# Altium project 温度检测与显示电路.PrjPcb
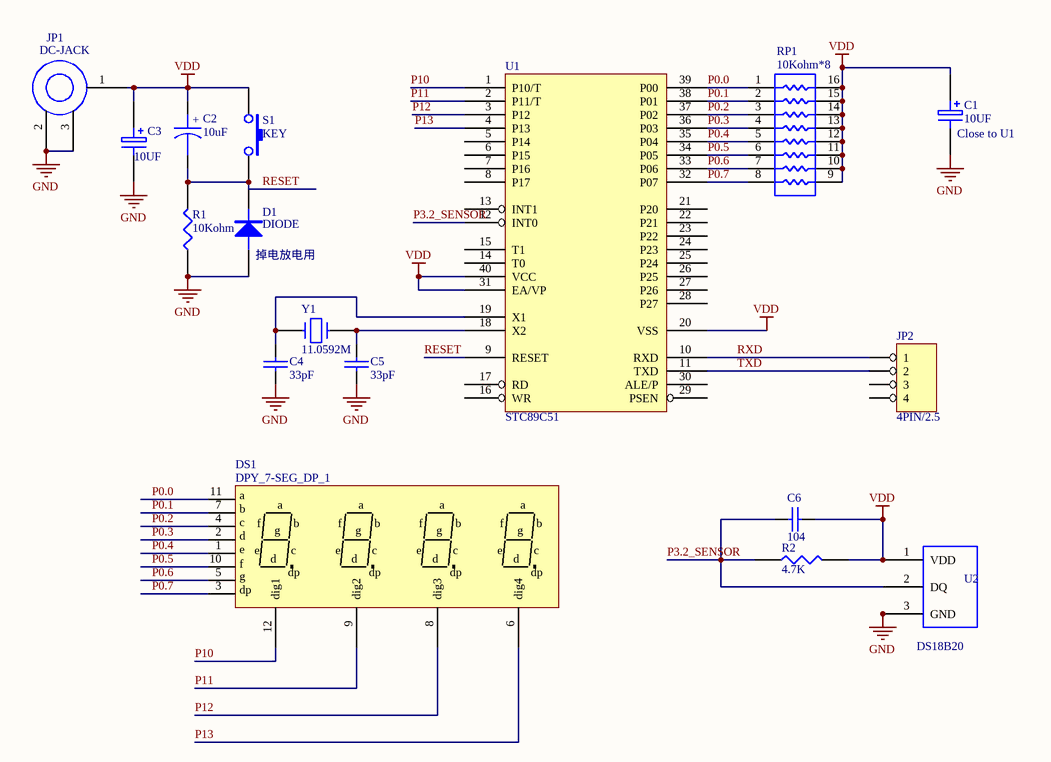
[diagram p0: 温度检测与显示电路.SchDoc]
1 sheet, 17 parts. Net scope: global (net labels, ports and power ports of the same name join across sheets).
Board file: 温度检测与显示电路.PcbDoc

## Sheet 温度检测与显示电路.SchDoc
size A4

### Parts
C1  10UF  [RB.1/.2 - ZJM]
C2  10uF  [rb.1/.2 - ZJM]
C3  10UF  [RB.1/.2 - ZJM]
C4  33pF  [rad-0.1]
C5  33pF  [rad-0.1]
C6  104  [RAD-0.1]
D1  DIODE  [DIODE-0.4]
DS1  DPY_7-SEG_DP_1  [DPY_7SEG_DP_4bit]
JP1  DC-JACK  [DC-JACK]
JP2  4PIN/2.5  [HDR1X2]
R1  10Kohm  [AXIAL-0.4]
R2  4.7K  [AXIAL-0.4]
RP1  10Kohm*8  [DIP-16]
S1  KEY  [KEY4.5*6.5]
U1  STC89C51  [STC89C51]
U2  DS18B20  [TO-92]
Y1  11.0592M  [XTAL11.0592M]

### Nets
GND: C1.2 C3.2 C4.2 C5.2 D1.1(A) JP1.2 JP1.3 R1.1 U2.3(GND)
VDD: C1.1 C2.1 C3.1 C6.2 JP1.1 R2.2 RP1.9 RP1.10 RP1.11 RP1.12 RP1.13 RP1.14 RP1.15 RP1.16 S1.1 U1.20(VSS) U1.31(EA/VP) U1.40(VCC) U2.1(VDD)
P0.0: DS1.11(a) RP1.1 U1.39(P00)
P0.1: DS1.7(b) RP1.2 U1.38(P01)
P0.2: DS1.4(c) RP1.3 U1.37(P02)
P0.3: DS1.2(d) RP1.4 U1.36(P03)
P0.4: DS1.1(e) RP1.5 U1.35(P04)
P0.5: DS1.10(f) RP1.6 U1.34(P05)
P0.6: DS1.5(g) RP1.7 U1.33(P06)
P0.7: DS1.3(dp) RP1.8 U1.32(P07)
P3.2_SENSOR: C6.1 R2.1 U1.12(INT0) U2.2(DQ)
P10: DS1.12(dig1) U1.1(P10/T)
P11: DS1.9(dig2) U1.2(P11/T)
P12: DS1.8(dig3) U1.3(P12)
P13: DS1.6(dig4) U1.4(P13)
RESET: C2.2 D1.2(K) R1.2 S1.2 U1.9(RESET)
RXD: JP2.1 U1.10(RXD)
TXD: JP2.2 U1.11(TXD)
NetC4_1: C4.1 U1.19(X1) Y1.1
NetC5_1: C5.1 U1.18(X2) Y1.2

Not connected (* = marked no-connect by the designer): JP2 3 4; U1 5(P14) 6(P15) 7(P16) 8(P17) 13(INT1) 14(T0) 15(T1) 16(WR) 17(RD) 21(P20) 22(P21) 23(P22) 24(P23) 25(P24) 26(P25) 27(P26) 28(P27) 29(PSEN) 30(ALE/P)

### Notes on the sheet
- (near C1) Close to U1
- (near D1) 掉电放电用

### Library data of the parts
C1 C3 = ELECTRO1: Electrolytic Capacitor
C2 = CAPACITOR POL: Capacitor
C4-C6 = CAP: Capacitor
DS1 = DPY_7-SEG_DP_1: Seven-Segment Display, Right Hand Decimal
JP2 = 4 HEADER: 4 Pin Header
R1 R2 = RES1
RP1 = RESPACK3
S1 = SW-PB
Y1 = CRYSTAL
